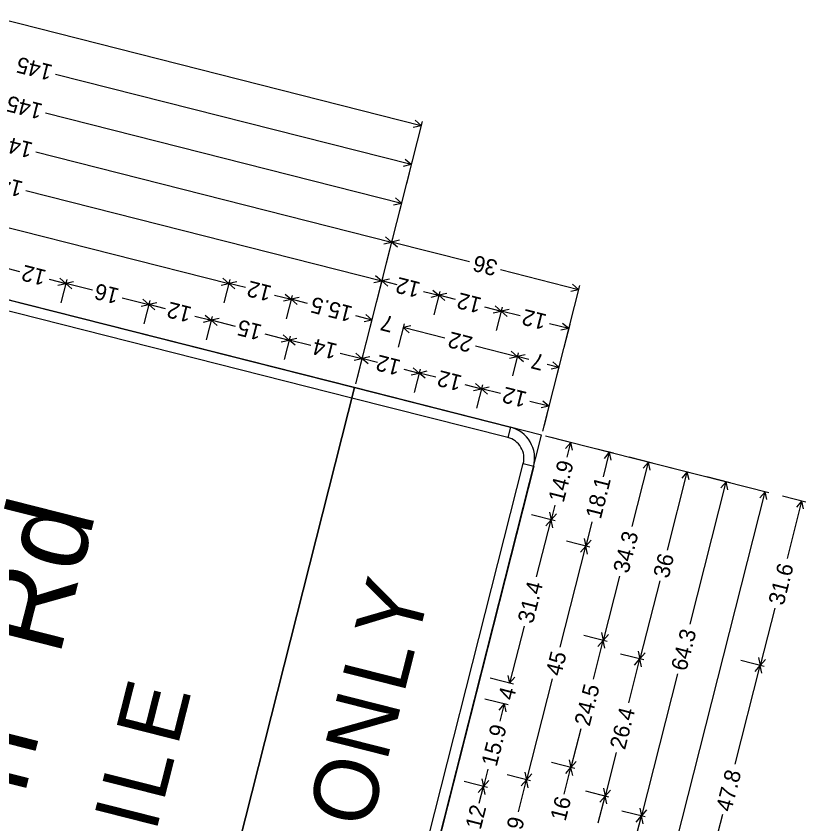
# Model space of a CAD drawing. Extents: x 670006 to 670131, y 737833 to 738003.
# Drawn here: x 670035.69 to 670060.25, y 737874.18 to 737899.3 of the extents above; entities that cross this region are included whole.
import ezdxf

# ---------------------------------------------------------------- set-up
doc = ezdxf.new("R2010")
doc.units = 0
doc.layers.add('R_SIGN', color=7, linetype='Continuous')

msp = doc.modelspace()

# ---------------------------------------------------------------- linework, layer by layer
at = {"layer": 'R_SIGN'}
for p, q in [((670034.875, 737899.302), (670048.281, 737895.902)), ((670036.911, 737897.499), (670047.975, 737894.693)), ((670036.605, 737896.291), (670047.668, 737893.485)), ((670048.312, 737896.022), (670046.243, 737887.865)), ((670048.092, 737896.064), (670048.281, 737895.902)), ((670048.038, 737895.848), (670048.281, 737895.902)), ((670036.298, 737895.082), (670047.362, 737892.276)), ((670046.212, 737887.745), (670018.102, 737894.874)), ((670047.786, 737894.856), (670047.975, 737894.693)), ((670048.005, 737894.814), (670047.822, 737894.089)), ((670047.731, 737894.64), (670047.975, 737894.693)), ((670035.992, 737893.874), (670047.055, 737891.068)), ((670047.425, 737893.431), (670047.668, 737893.485)), ((670047.48, 737893.648), (670047.668, 737893.485)), ((670047.699, 737893.606), (670047.515, 737892.88)), ((670033.753, 737893.155), (670042.302, 737890.987)), ((670047.392, 737892.397), (670046.243, 737887.865)), ((670047.118, 737892.223), (670047.362, 737892.276)), ((670047.173, 737892.439), (670047.362, 737892.276)), ((670047.392, 737892.397), (670047.209, 737891.672)), ((670047.605, 737892.329), (670047.362, 737892.276)), ((670049.788, 737891.661), (670047.362, 737892.276)), ((670047.55, 737892.113), (670047.362, 737892.276)), ((670035.806, 737891.349), (670035.291, 737891.479)), ((670046.867, 737891.231), (670047.055, 737891.068)), ((670050.751, 737891.417), (670053.178, 737890.801)), ((670036.715, 737891.118), (670037.23, 737890.987)), ((670036.986, 737890.934), (670037.23, 737890.987)), ((670037.041, 737891.15), (670037.23, 737890.987)), ((670037.26, 737891.108), (670037.077, 737890.383)), ((670037.473, 737891.041), (670037.23, 737890.987)), ((670038.062, 737890.776), (670037.23, 737890.987)), ((670037.419, 737890.824), (670037.23, 737890.987)), ((670042.058, 737890.934), (670042.302, 737890.987)), ((670042.113, 737891.15), (670042.302, 737890.987)), ((670042.333, 737891.108), (670042.149, 737890.383)), ((670042.546, 737891.04), (670042.302, 737890.987)), ((670042.816, 737890.857), (670042.302, 737890.987)), ((670042.491, 737890.824), (670042.302, 737890.987)), ((670046.812, 737891.015), (670047.055, 737891.068)), ((670047.086, 737891.189), (670046.902, 737890.464)), ((670047.086, 737891.189), (670046.902, 737890.464)), ((670047.299, 737891.121), (670047.055, 737891.068)), ((670047.536, 737890.946), (670047.055, 737891.068)), ((670047.244, 737890.905), (670047.055, 737891.068)), ((670052.989, 737890.964), (670053.178, 737890.801)), ((670048.352, 737890.739), (670048.832, 737890.617)), ((670048.644, 737890.78), (670048.832, 737890.617)), ((670048.863, 737890.738), (670048.679, 737890.013)), ((670053.208, 737890.922), (670052.059, 737886.39)), ((670052.934, 737890.748), (670053.178, 737890.801)), ((670038.982, 737890.543), (670039.815, 737890.332)), ((670039.626, 737890.495), (670039.815, 737890.332)), ((670043.726, 737890.626), (670044.241, 737890.495)), ((670043.997, 737890.442), (670044.241, 737890.495)), ((670044.052, 737890.658), (670044.241, 737890.495)), ((670044.271, 737890.616), (670044.087, 737889.891)), ((670044.271, 737890.616), (670044.087, 737889.891)), ((670044.484, 737890.549), (670044.241, 737890.495)), ((670044.746, 737890.367), (670044.241, 737890.495)), ((670044.429, 737890.332), (670044.241, 737890.495)), ((670048.589, 737890.564), (670048.832, 737890.617)), ((670049.076, 737890.67), (670048.832, 737890.617)), ((670049.347, 737890.487), (670048.832, 737890.617)), ((670049.021, 737890.454), (670048.832, 737890.617)), ((670039.571, 737890.278), (670039.815, 737890.332)), ((670039.845, 737890.453), (670039.661, 737889.728)), ((670040.058, 737890.385), (670039.815, 737890.332)), ((670040.329, 737890.201), (670039.815, 737890.332)), ((670040.003, 737890.169), (670039.815, 737890.332)), ((670050.257, 737890.256), (670050.771, 737890.125)), ((670050.582, 737890.288), (670050.771, 737890.125)), ((670050.802, 737890.246), (670050.618, 737889.521)), ((670050.802, 737890.246), (670050.618, 737889.521)), ((670041.239, 737889.971), (670041.753, 737889.84)), ((670041.564, 737890.003), (670041.753, 737889.84)), ((670041.784, 737889.961), (670041.6, 737889.236)), ((670046.243, 737889.988), (670046.749, 737889.859)), ((670046.56, 737890.022), (670046.749, 737889.859)), ((670046.779, 737889.98), (670046.596, 737889.255)), ((670046.779, 737889.98), (670046.596, 737889.255)), ((670050.527, 737890.072), (670050.771, 737890.125)), ((670051.015, 737890.179), (670050.771, 737890.125)), ((670051.364, 737889.975), (670050.771, 737890.125)), ((670050.96, 737889.963), (670050.771, 737890.125)), ((670041.51, 737889.787), (670041.753, 737889.84)), ((670041.997, 737889.893), (670041.753, 737889.84)), ((670042.507, 737889.649), (670041.753, 737889.84)), ((670041.942, 737889.677), (670041.753, 737889.84)), ((670046.505, 737889.806), (670046.749, 737889.859)), ((670047.749, 737889.734), (670047.565, 737889.009)), ((670052.278, 737889.743), (670052.871, 737889.593)), ((670052.682, 737889.756), (670052.871, 737889.593)), ((670052.902, 737889.714), (670052.718, 737888.989)), ((670047.962, 737889.667), (670047.718, 737889.614)), ((670049.014, 737889.285), (670047.718, 737889.614)), ((670047.907, 737889.45), (670047.718, 737889.614)), ((670052.628, 737889.54), (670052.871, 737889.593)), ((670043.422, 737889.417), (670044.177, 737889.225)), ((670043.933, 737889.172), (670044.177, 737889.225)), ((670043.988, 737889.388), (670044.177, 737889.225)), ((670044.207, 737889.346), (670044.023, 737888.621)), ((670044.207, 737889.346), (670044.023, 737888.621)), ((670044.42, 737889.279), (670044.177, 737889.225)), ((670044.855, 737889.054), (670044.177, 737889.225)), ((670044.365, 737889.063), (670044.177, 737889.225)), ((670049.977, 737889.041), (670051.272, 737888.712)), ((670045.764, 737888.823), (670046.442, 737888.651)), ((670046.254, 737888.814), (670046.442, 737888.651)), ((670046.473, 737888.772), (670046.289, 737888.047)), ((670046.473, 737888.772), (670046.289, 737888.047)), ((670046.686, 737888.704), (670046.442, 737888.651)), ((670051.029, 737888.659), (670051.272, 737888.712)), ((670051.083, 737888.875), (670051.272, 737888.712)), ((670051.303, 737888.833), (670051.119, 737888.108)), ((670051.303, 737888.833), (670051.119, 737888.108)), ((670051.516, 737888.765), (670051.272, 737888.712)), ((670051.631, 737888.621), (670051.272, 737888.712)), ((670051.461, 737888.549), (670051.272, 737888.712)), ((670046.199, 737888.598), (670046.442, 737888.651)), ((670046.923, 737888.529), (670046.442, 737888.651)), ((670046.631, 737888.488), (670046.442, 737888.651)), ((670052.206, 737888.475), (670052.565, 737888.384)), ((670052.376, 737888.547), (670052.565, 737888.384)), ((670052.595, 737888.505), (670052.411, 737887.78)), ((670047.739, 737888.322), (670048.219, 737888.2)), ((670047.976, 737888.147), (670048.219, 737888.2)), ((670048.031, 737888.363), (670048.219, 737888.2)), ((670048.25, 737888.321), (670048.066, 737887.596)), ((670048.463, 737888.253), (670048.219, 737888.2)), ((670048.734, 737888.07), (670048.219, 737888.2)), ((670048.408, 737888.037), (670048.219, 737888.2)), ((670052.321, 737888.331), (670052.565, 737888.384)), ((670037.854, 737854.788), (670046.212, 737887.745)), ((670046.212, 737887.745), (670037.854, 737854.788)), ((670052.028, 737886.269), (670046.212, 737887.745)), ((670049.644, 737887.839), (670050.158, 737887.708)), ((670049.914, 737887.655), (670050.158, 737887.708)), ((670049.969, 737887.871), (670050.158, 737887.708)), ((670050.189, 737887.829), (670050.005, 737887.104)), ((670050.189, 737887.829), (670050.005, 737887.104)), ((670050.402, 737887.762), (670050.158, 737887.708)), ((670050.751, 737887.558), (670050.158, 737887.708)), ((670050.347, 737887.546), (670050.158, 737887.708)), ((670051.665, 737887.326), (670052.258, 737887.176)), ((670052.069, 737887.339), (670052.258, 737887.176)), ((670052.289, 737887.297), (670052.105, 737886.572)), ((670052.015, 737887.123), (670052.258, 737887.176)), ((670051.059, 737886.515), (670050.977, 737886.192)), ((670043.67, 737853.313), (670052.028, 737886.269)), ((670059.098, 737884.476), (670052.149, 737886.239)), ((670053.055, 737886.009), (670052.33, 737886.193)), ((670052.772, 737885.851), (670052.935, 737886.04)), ((670052.819, 737885.584), (670052.935, 737886.04)), ((670052.988, 737885.796), (670052.935, 737886.04)), ((670054.264, 737885.702), (670053.539, 737885.886)), ((670053.95, 737884.972), (670054.143, 737885.733)), ((670053.98, 737885.544), (670054.143, 737885.733)), ((670054.196, 737885.49), (670054.143, 737885.733)), ((670055.472, 737885.396), (670054.747, 737885.58)), ((670051.459, 737885.382), (670051.782, 737885.3)), ((670054.844, 737883.424), (670055.352, 737885.427)), ((670055.189, 737885.238), (670055.352, 737885.427)), ((670055.405, 737885.183), (670055.352, 737885.427)), ((670056.681, 737885.089), (670055.956, 737885.273)), ((670055.945, 737882.694), (670056.56, 737885.12)), ((670056.397, 737884.931), (670056.56, 737885.12)), ((670056.613, 737884.877), (670056.56, 737885.12)), ((670057.889, 737884.783), (670057.164, 737884.967)), ((670056.646, 737880.389), (670057.768, 737884.814)), ((670057.606, 737884.625), (670057.768, 737884.814)), ((670057.822, 737884.57), (670057.768, 737884.814)), ((670054.969, 737868.704), (670058.977, 737884.507)), ((670058.814, 737884.318), (670058.977, 737884.507)), ((670059.03, 737884.264), (670058.977, 737884.507)), ((670060.246, 737884.185), (670059.521, 737884.369)), ((670059.673, 737882.433), (670060.125, 737884.216)), ((670059.962, 737884.027), (670060.125, 737884.216)), ((670060.178, 737883.972), (670060.125, 737884.216)), ((670052.439, 737884.087), (670052.324, 737883.631)), ((670052.445, 737883.6), (670051.719, 737883.784)), ((670052.445, 737883.6), (670051.719, 737883.784)), ((670052.27, 737883.874), (670052.324, 737883.631)), ((670052.487, 737883.82), (670052.324, 737883.631)), ((670051.874, 737881.859), (670052.324, 737883.631)), ((670052.161, 737883.442), (670052.324, 737883.631)), ((670052.377, 737883.387), (670052.324, 737883.631)), ((670053.595, 737883.573), (670053.402, 737882.812)), ((670053.523, 737882.782), (670052.798, 737882.966)), ((670053.523, 737882.782), (670052.798, 737882.966)), ((670053.349, 737883.056), (670053.402, 737882.812)), ((670053.565, 737883.001), (670053.402, 737882.812)), ((670052.605, 737879.668), (670053.402, 737882.812)), ((670053.239, 737882.624), (670053.402, 737882.812)), ((670053.456, 737882.569), (670053.402, 737882.812)), ((670054.453, 737881.884), (670053.945, 737879.882)), ((670055.7, 737881.731), (670055.085, 737879.304)), ((670059.281, 737880.888), (670058.829, 737879.104)), ((670051.485, 737880.324), (670051.035, 737878.552)), ((670054.066, 737879.852), (670053.341, 737880.035)), ((670054.066, 737879.852), (670053.341, 737880.035)), ((670053.892, 737880.126), (670053.945, 737879.882)), ((670054.108, 737880.071), (670053.945, 737879.882)), ((670053.64, 737878.68), (670053.945, 737879.882)), ((670053.782, 737879.693), (670053.945, 737879.882)), ((670053.999, 737879.639), (670053.945, 737879.882)), ((670055.206, 737879.274), (670054.481, 737879.458)), ((670055.206, 737879.274), (670054.481, 737879.458)), ((670055.032, 737879.548), (670055.085, 737879.304)), ((670055.248, 737879.493), (670055.085, 737879.304)), ((670054.74, 737877.944), (670055.085, 737879.304)), ((670054.922, 737879.116), (670055.085, 737879.304)), ((670055.138, 737879.061), (670055.085, 737879.304)), ((670058.949, 737879.074), (670058.224, 737879.258)), ((670058.949, 737879.074), (670058.224, 737879.258)), ((670058.775, 737879.348), (670058.829, 737879.104)), ((670058.991, 737879.293), (670058.829, 737879.104)), ((670058.048, 737876.028), (670058.829, 737879.104)), ((670058.666, 737878.916), (670058.829, 737879.104)), ((670058.882, 737878.861), (670058.829, 737879.104)), ((670051.156, 737878.521), (670050.431, 737878.705)), ((670050.982, 737878.795), (670051.035, 737878.552)), ((670051.198, 737878.74), (670051.035, 737878.552)), ((670052.356, 737878.687), (670051.558, 737875.542)), ((670056.255, 737878.844), (670055.132, 737874.42)), ((670050.992, 737877.875), (670050.267, 737878.059)), ((670050.709, 737877.717), (670050.872, 737877.905)), ((670050.736, 737877.37), (670050.872, 737877.905)), ((670050.925, 737877.662), (670050.872, 737877.905)), ((670053.247, 737877.13), (670052.942, 737875.927)), ((670054.348, 737876.399), (670054.003, 737875.039)), ((670052.889, 737876.171), (670052.942, 737875.927)), ((670053.063, 737875.897), (670052.338, 737876.081)), ((670052.731, 737875.095), (670052.942, 737875.927)), ((670052.779, 737875.739), (670052.942, 737875.927)), ((670053.105, 737876.116), (670052.942, 737875.927)), ((670052.996, 737875.684), (670052.942, 737875.927)), ((670050.356, 737875.873), (670050.22, 737875.337)), ((670051.679, 737875.512), (670050.954, 737875.696)), ((670051.505, 737875.786), (670051.558, 737875.542)), ((670051.721, 737875.731), (670051.558, 737875.542)), ((670050.341, 737875.306), (670049.616, 737875.49)), ((670050.167, 737875.58), (670050.22, 737875.337)), ((670050.383, 737875.526), (670050.22, 737875.337)), ((670051.307, 737874.55), (670051.558, 737875.542)), ((670051.396, 737875.354), (670051.558, 737875.542)), ((670051.612, 737875.299), (670051.558, 737875.542)), ((670050.057, 737875.148), (670050.22, 737875.337)), ((670050.09, 737874.822), (670050.22, 737875.337)), ((670050.273, 737875.093), (670050.22, 737875.337)), ((670054.124, 737875.009), (670053.399, 737875.193)), ((670053.95, 737875.283), (670054.003, 737875.039)), ((670054.166, 737875.228), (670054.003, 737875.039)), ((670053.792, 737874.207), (670054.003, 737875.039)), ((670053.84, 737874.851), (670054.003, 737875.039)), ((670054.057, 737874.796), (670054.003, 737875.039)), ((670055.079, 737874.664), (670055.132, 737874.42)), ((670054.438, 737871.681), (670055.132, 737874.42)), ((670055.253, 737874.39), (670054.528, 737874.573)), ((670055.253, 737874.39), (670054.528, 737874.573)), ((670054.97, 737874.231), (670055.132, 737874.42)), ((670055.295, 737874.609), (670055.132, 737874.42)), ((670055.186, 737874.177), (670055.132, 737874.42)), ((670057.652, 737874.465), (670056.872, 737871.389))]:
    msp.add_line(p, q, dxfattribs=at)
for points in [[(670046.13, 737887.421), (670018.99, 737894.305), (670019.072, 737894.628), (670046.212, 737887.745), (670046.13, 737887.421)], [(670050.977, 737886.192), (670046.13, 737887.421), (670046.212, 737887.745), (670051.059, 737886.515), (670050.977, 737886.192)], [(670043.592, 737854.364), (670051.459, 737885.382), (670051.782, 737885.3), (670043.916, 737854.282), (670043.592, 737854.364)]]:
    msp.add_lwpolyline(points, close=True, dxfattribs=at)
for radius in [1, 0.667]:
    msp.add_arc((670050.813, 737885.546), radius, 345.7686, 75.7688, dxfattribs=at)

# ---------------------------------------------------------------- texts
for s, height, rotation, p in [('145', 0.4987, 165.7688, (670036.852, 737897.771)), ('145', 0.4987, 165.7688, (670036.545, 737896.563)), ('145', 0.4987, 165.7688, (670036.239, 737895.355)), ('145', 0.4987, 165.7688, (670035.932, 737894.146)), ('36', 0.4987, 165.7688, (670050.692, 737891.689)), ('12', 0.4987, 165.7688, (670036.656, 737891.39)), ('16', 0.4987, 165.7688, (670038.923, 737890.815)), ('12', 0.4987, 165.7688, (670043.667, 737890.898)), ('12', 0.4987, 165.7688, (670048.292, 737891.011)), ('15.5', 0.4987, 165.7688, (670046.184, 737890.26)), ('12', 0.4987, 165.7688, (670050.197, 737890.528)), ('12', 0.4987, 165.7688, (670041.179, 737890.243)), ('7', 0.499, 165.7688, (670047.464, 737889.935)), ('12', 0.4987, 165.7688, (670052.219, 737890.015)), ('15', 0.4987, 165.7688, (670043.363, 737889.689)), ('22', 0.4987, 165.7688, (670049.917, 737889.313)), ('14', 0.4987, 165.7688, (670045.705, 737889.095)), ('12', 0.4987, 165.7688, (670047.679, 737888.594)), ('7', 0.499, 165.7688, (670052.147, 737888.748)), ('12', 0.4987, 165.7688, (670049.584, 737888.111)), ('12', 0.4987, 165.7688, (670051.606, 737887.598)), ('14.9', 0.4987, 75.7686, (670052.712, 737884.146)), ('18.1', 0.4987, 75.7686, (670053.868, 737883.633)), ('d', 2.667, 75.7686, (670037.677, 737881.904)), ('34.3', 0.4987, 75.7686, (670054.725, 737881.944)), ('36', 0.4987, 75.7686, (670055.973, 737881.79)), ('31.6', 0.4987, 75.7686, (670059.553, 737880.947)), ('R', 2.667, 75.7686, (670037.028, 737879.345)), ('Y', 2, 75.7686, (670048.135, 737879.733)), ('31.4', 0.4987, 75.7686, (670051.757, 737880.383)), ('64.3', 0.4987, 75.7686, (670056.527, 737878.904)), ('L', 2, 75.7686, (670047.742, 737878.182)), ('45', 0.4987, 75.7686, (670052.628, 737878.747)), ('E', 2, 75.7686, (670040.704, 737876.553)), ('24.5', 0.4987, 75.7686, (670053.52, 737877.189)), ('N', 2, 75.7686, (670047.206, 737876.069)), ('4', 0.499, 75.7686, (670051.151, 737877.994)), ('26.4', 0.4987, 75.7686, (670054.621, 737876.459)), ('n', 2.667, 75.7686, (670035.94, 737875.054)), ('15.9', 0.4987, 75.7686, (670050.628, 737875.932)), ('L', 2, 75.7686, (670040.262, 737874.808)), ('O', 2, 75.7686, (670046.675, 737873.975)), ('47.8', 0.4987, 75.7686, (670057.924, 737874.525)), ('16', 0.4987, 75.7686, (670052.77, 737874.235)), ('I', 2, 75.7686, (670040.026, 737873.877)), ('12', 0.4987, 75.7686, (670050.131, 737873.972)), ('21.9', 0.4987, 75.7686, (670051.186, 737873.059))]:
    msp.add_text(s, height=height, rotation=rotation, dxfattribs=at).set_placement(p)

doc.saveas('drawing.dxf')
